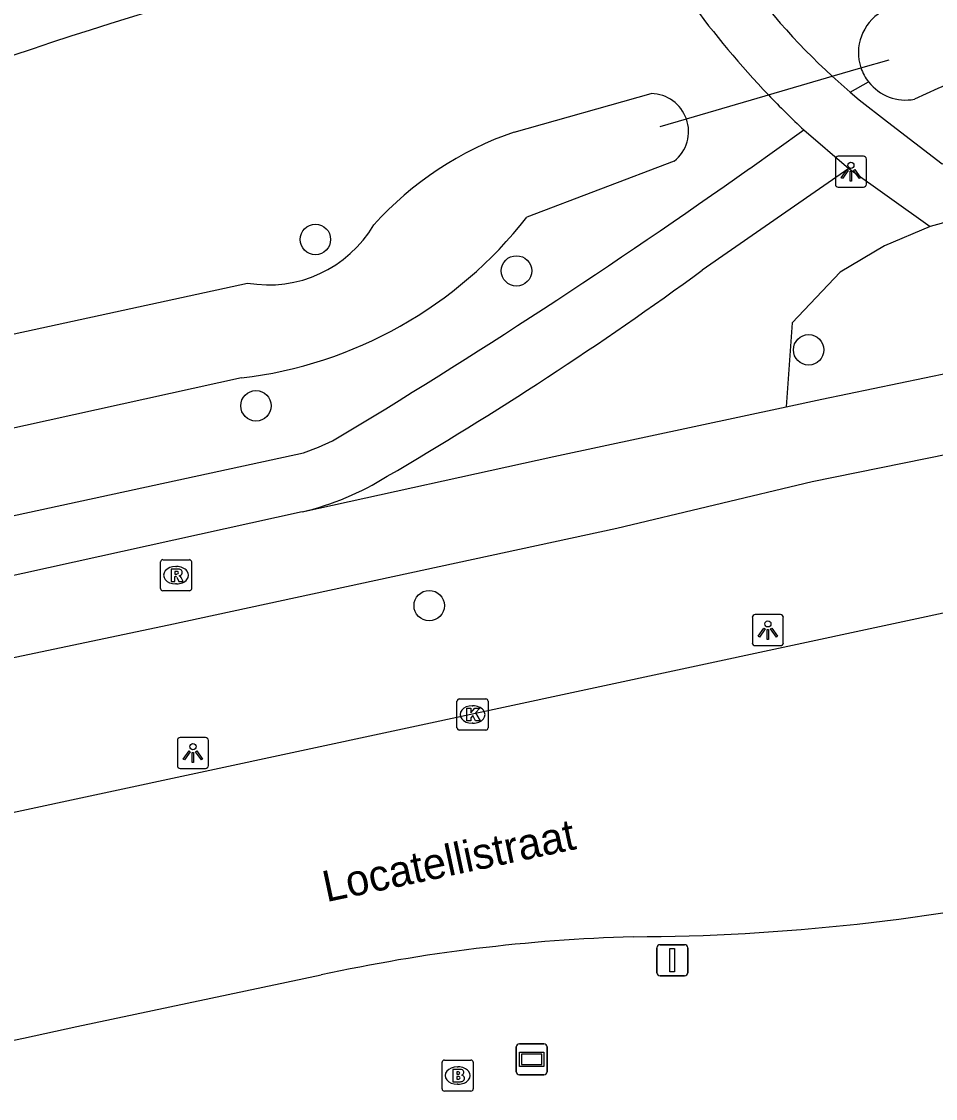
# Model space of a CAD drawing. Extents: x 159053 to 160041, y 380450 to 381422.
# Drawn here: x 159231.84 to 159261.22, y 380743.22 to 380777.85 of the extents above; entities that cross this region are included whole.
import ezdxf

# ---------------------------------------------------------------- set-up
doc = ezdxf.new("R2010")
doc.units = 0
for name, color, linetype in [('IMGEO_Boom', 7, 'Continuous'), ('IMGEO_Brandkraan', 7, 'Continuous'), ('IMGEO_Duiker', 7, 'Continuous'), ('IMGEO_Fietspad_gesloten', 7, 'Continuous'), ('IMGEO_Groenvoorziening', 7, 'Continuous'), ('IMGEO_Kolk', 7, 'Continuous'), ('IMGEO_Lichtpunt', 7, 'Continuous'), ('IMGEO_Openbare_ruimte_label', 7, 'Continuous'), ('IMGEO_Rijbaan_lokaal_gesloten', 7, 'Continuous'), ('IMGEO_Rioolput', 7, 'Continuous'), ('IMGEO_Verkeersbordpaal', 7, 'Continuous'), ('IMGEO_Verklikker', 7, 'Continuous'), ('IMGEO_Voetpad_open', 7, 'Continuous'), ('IMGEO_Waterloop', 7, 'Continuous')]:
    doc.layers.add(name, color=color, linetype=linetype)

msp = doc.modelspace()

# ---------------------------------------------------------------- linework, layer by layer
at = {"layer": 'IMGEO_Boom'}
for centre in [(159241.291, 380770.84), (159247.754, 380769.829), (159257.145, 380767.29), (159239.38, 380765.491), (159244.949, 380759.065)]:
    msp.add_circle(centre, 0.489, dxfattribs=at)
at = {"layer": 'IMGEO_Brandkraan'}
for p, q in [((159245.438, 380744.453), (159246.29, 380744.453)), ((159245.363, 380743.527), (159245.363, 380744.379)), ((159245.851, 380744.233), (159245.876, 380744.233)), ((159246.364, 380744.379), (159246.364, 380743.527)), ((159246.29, 380743.453), (159245.438, 380743.453)), ((159245.874, 380743.673), (159245.849, 380743.673))]:
    msp.add_line(p, q, dxfattribs=at)
for points in [[(159245.438, 380744.453), (159246.29, 380744.453)], [(159245.363, 380743.527), (159245.363, 380744.379)], [(159245.711, 380744.153), (159245.711, 380743.753), (159245.924, 380743.753)], [(159245.942, 380744.153), (159245.711, 380744.153)], [(159246.364, 380744.379), (159246.364, 380743.527)], [(159245.89, 380744.072), (159245.836, 380744.072), (159245.836, 380743.996)], [(159245.836, 380743.996), (159245.889, 380743.996)], [(159245.898, 380743.92), (159245.836, 380743.92), (159245.836, 380743.839)], [(159245.836, 380743.839), (159245.898, 380743.839)], [(159246.29, 380743.453), (159245.438, 380743.453)]]:
    msp.add_lwpolyline(points, dxfattribs=at)
for centre, radius, start, end in [((159245.44, 380744.377), 0.0765, 91.552, 178.448), ((159245.44, 380744.377), 0.0765, 91.552, 178.448), ((159246.288, 380744.377), 0.0765, 1.552, 88.448), ((159246.288, 380744.377), 0.0765, 1.552, 88.448), ((159245.946, 380744.008), 0.145, 59.4692, 91.5367), ((159245.971, 380744.055), 0.0922, 285.5137, 58.1501), ((159245.891, 380744.034), 0.0379, 267.8285, 90.9355), ((159245.899, 380743.879), 0.0404, 269.8759, 90.5077), ((159245.93, 380744.004), 0.251, 268.6676, 293.5347), ((159245.976, 380743.863), 0.105, 301.3115, 78.989), ((159245.44, 380743.529), 0.0765, 181.552, 268.448), ((159245.44, 380743.529), 0.0765, 181.552, 268.448), ((159246.288, 380743.529), 0.0765, 271.552, 358.448), ((159246.288, 380743.529), 0.0765, 271.552, 358.448)]:
    msp.add_arc(centre, radius, start, end, dxfattribs=at)
for centre, major_axis, ratio, start_param, end_param in [((159245.85, 380743.953), (-0.387, 0.002), 0.722429, 4.712389, 7.853982), ((159245.875, 380743.953), (-0.39, 0.002), 0.717154, 1.570796, 4.712389)]:
    msp.add_ellipse(centre, major_axis=major_axis, ratio=ratio, start_param=start_param, end_param=end_param, dxfattribs=at)
at = {"layer": 'IMGEO_Duiker'}
msp.add_lwpolyline([(159252.374, 380774.473), (159253.216, 380774.719), (159255.747, 380775.458), (159255.854, 380775.489), (159257.719, 380776.033), (159257.904, 380776.087), (159258.828, 380776.357), (159259.732, 380776.621)], dxfattribs=at)
at = {"layer": 'IMGEO_Fietspad_gesloten'}
for points in [[(159256.423, 380765.457), (159257.575, 380765.703), (159263.34, 380766.906)], [(159240.86, 380762.077), (159248.952, 380763.865), (159256.423, 380765.457)], [(159215.224, 380754.658), (159220.197, 380755.183), (159224.095, 380755.817), (159236.577, 380758.45), (159250.976, 380761.561), (159257.264, 380763.056), (159263.863, 380764.398)], [(159240.86, 380762.077), (159228.577, 380759.365), (159223.632, 380758.213), (159221.177, 380757.811)]]:
    msp.add_lwpolyline(points, dxfattribs=at)
at = {"layer": 'IMGEO_Groenvoorziening'}
for points in [[(159258.48, 380775.578), (159259.075, 380775.904)], [(159261.051, 380771.257), (159259.589, 380770.637), (159258.163, 380769.793), (159256.621, 380768.163), (159256.423, 380765.457)]]:
    msp.add_lwpolyline(points, dxfattribs=at)
at = {"layer": 'IMGEO_Kolk'}
for p, q in [((159245.842, 380755.138), (159245.842, 380755.99)), ((159245.917, 380756.064), (159246.769, 380756.064)), ((159246.843, 380755.99), (159246.843, 380755.138)), ((159246.33, 380755.844), (159246.355, 380755.844)), ((159246.353, 380755.284), (159246.328, 380755.284)), ((159246.769, 380755.064), (159245.917, 380755.064))]:
    msp.add_line(p, q, dxfattribs=at)
for points in [[(159245.842, 380755.138), (159245.842, 380755.99)], [(159245.917, 380756.064), (159246.769, 380756.064)], [(159246.843, 380755.99), (159246.843, 380755.138)], [(159246.163, 380755.764), (159246.286, 380755.764), (159246.286, 380755.613), (159246.416, 380755.764), (159246.58, 380755.764), (159246.434, 380755.613), (159246.587, 380755.364), (159246.435, 380755.364), (159246.35, 380755.528), (159246.286, 380755.461), (159246.286, 380755.364), (159246.163, 380755.364), (159246.163, 380755.764)], [(159246.769, 380755.064), (159245.917, 380755.064)]]:
    msp.add_lwpolyline(points, dxfattribs=at)
for centre, start, end in [((159245.919, 380755.988), 91.552, 178.448), ((159245.919, 380755.988), 91.552, 178.448), ((159246.767, 380755.988), 1.552, 88.448), ((159246.767, 380755.988), 1.552, 88.448), ((159245.919, 380755.14), 181.552, 268.448), ((159245.919, 380755.14), 181.552, 268.448), ((159246.767, 380755.14), 271.552, 358.448), ((159246.767, 380755.14), 271.552, 358.448)]:
    msp.add_arc(centre, 0.0765, start, end, dxfattribs=at)
for centre, major_axis, ratio, start_param, end_param in [((159246.329, 380755.564), (-0.387, 0.002), 0.722429, 4.712389, 7.853982), ((159246.354, 380755.564), (-0.39, 0.002), 0.717154, 1.570796, 4.712389)]:
    msp.add_ellipse(centre, major_axis=major_axis, ratio=ratio, start_param=start_param, end_param=end_param, dxfattribs=at)
at = {"layer": 'IMGEO_Lichtpunt'}
for p, q in [((159258.005, 380773.424), (159258.005, 380772.617)), ((159258.005, 380773.424), (159258.005, 380772.617)), ((159258.907, 380773.519), (159258.099, 380773.519)), ((159258.907, 380773.519), (159258.099, 380773.519)), ((159259.001, 380772.617), (159259.001, 380773.424)), ((159259.001, 380772.617), (159259.001, 380773.424)), ((159258.099, 380772.523), (159258.907, 380772.523)), ((159258.099, 380772.523), (159258.907, 380772.523)), ((159255.336, 380758.681), (159255.336, 380757.874)), ((159255.336, 380758.681), (159255.336, 380757.874)), ((159256.238, 380758.776), (159255.43, 380758.776)), ((159256.238, 380758.776), (159255.43, 380758.776)), ((159256.332, 380757.874), (159256.332, 380758.681)), ((159256.332, 380757.874), (159256.332, 380758.681)), ((159255.43, 380757.78), (159256.238, 380757.78)), ((159255.43, 380757.78), (159256.238, 380757.78)), ((159236.854, 380754.729), (159236.854, 380753.922)), ((159236.854, 380754.729), (159236.854, 380753.922)), ((159237.756, 380754.824), (159236.948, 380754.824)), ((159237.756, 380754.824), (159236.948, 380754.824)), ((159237.85, 380753.922), (159237.85, 380754.729)), ((159237.85, 380753.922), (159237.85, 380754.729)), ((159236.948, 380753.828), (159237.756, 380753.828)), ((159236.948, 380753.828), (159237.756, 380753.828))]:
    msp.add_line(p, q, dxfattribs=at)
for points in [[(159258.379, 380773.088), (159258.418, 380773.06), (159258.23, 380772.798), (159258.192, 380772.825), (159258.379, 380773.088)], [(159258.481, 380773.04), (159258.528, 380773.04), (159258.528, 380772.718), (159258.481, 380772.718), (159258.481, 380773.04)], [(159258.591, 380773.06), (159258.629, 380773.087), (159258.816, 380772.825), (159258.777, 380772.797), (159258.591, 380773.06)], [(159255.71, 380758.345), (159255.749, 380758.317), (159255.561, 380758.055), (159255.523, 380758.082), (159255.71, 380758.345)], [(159255.812, 380758.297), (159255.859, 380758.297), (159255.859, 380757.975), (159255.812, 380757.975), (159255.812, 380758.297)], [(159255.922, 380758.317), (159255.96, 380758.344), (159256.147, 380758.082), (159256.108, 380758.054), (159255.922, 380758.317)], [(159237.228, 380754.393), (159237.267, 380754.365), (159237.079, 380754.103), (159237.041, 380754.13), (159237.228, 380754.393)], [(159237.33, 380754.345), (159237.377, 380754.345), (159237.377, 380754.023), (159237.33, 380754.023), (159237.33, 380754.345)], [(159237.44, 380754.365), (159237.478, 380754.392), (159237.665, 380754.13), (159237.626, 380754.102), (159237.44, 380754.365)]]:
    msp.add_lwpolyline(points, dxfattribs=at)
for centre in [(159258.504, 380773.222), (159255.835, 380758.479), (159237.353, 380754.527)]:
    msp.add_circle(centre, 0.0994, dxfattribs=at)
for centre, start, end in [((159258.099, 380773.424), 90, 180), ((159258.099, 380773.424), 90, 180), ((159258.907, 380773.424), 0, 90), ((159258.907, 380773.424), 0, 90), ((159258.099, 380772.617), 180, 270), ((159258.099, 380772.617), 180, 270), ((159258.907, 380772.617), 270, 0), ((159258.907, 380772.617), 270, 360), ((159255.43, 380758.681), 90, 180), ((159255.43, 380758.681), 90, 180), ((159256.238, 380758.681), 0, 90), ((159256.238, 380758.681), 0, 90), ((159255.43, 380757.874), 180, 270), ((159255.43, 380757.874), 180, 270), ((159256.238, 380757.874), 270, 0), ((159256.238, 380757.874), 270, 360), ((159236.948, 380754.729), 90, 180), ((159236.948, 380754.729), 90, 180), ((159237.756, 380754.729), 0, 90), ((159237.756, 380754.729), 0, 90), ((159236.948, 380753.922), 180, 270), ((159236.948, 380753.922), 180, 270), ((159237.756, 380753.922), 270, 0), ((159237.756, 380753.922), 270, 360)]:
    msp.add_arc(centre, 0.0946, start, end, dxfattribs=at)
at = {"layer": 'IMGEO_Rijbaan_lokaal_gesloten'}
for points in [[(159265.764, 380759.746), (159225.045, 380751.009), (159219.931, 380750)], [(159223.158, 380743.217), (159226.529, 380744.028), (159231.908, 380745.154), (159233.625, 380745.533), (159241.475, 380747.19)]]:
    msp.add_lwpolyline(points, dxfattribs=at)
for centre, radius, start, end in [((159251.289, 380815.931), 67.514, 270.1809, 282.4292), ((159253.137, 380693.52), 54.922, 91.7055, 102.2589)]:
    msp.add_arc(centre, radius, start, end, dxfattribs=at)
at = {"layer": 'IMGEO_Rioolput'}
for p, q in [((159236.312, 380759.617), (159236.312, 380760.469)), ((159236.387, 380760.543), (159237.239, 380760.543)), ((159237.313, 380760.469), (159237.313, 380759.617)), ((159236.8, 380760.323), (159236.825, 380760.323)), ((159236.823, 380759.763), (159236.798, 380759.763)), ((159237.239, 380759.543), (159236.387, 380759.543))]:
    msp.add_line(p, q, dxfattribs=at)
for points in [[(159236.312, 380759.617), (159236.312, 380760.469)], [(159236.387, 380760.543), (159237.239, 380760.543)], [(159237.313, 380760.469), (159237.313, 380759.617)], [(159236.901, 380760.241), (159236.649, 380760.243), (159236.649, 380759.843)], [(159236.827, 380760.162), (159236.773, 380760.162), (159236.773, 380760.081)], [(159236.773, 380760.081), (159236.825, 380760.081)], [(159236.649, 380759.843), (159236.773, 380759.843), (159236.773, 380760.005), (159236.784, 380760.005)], [(159236.831, 380759.976), (159236.902, 380759.843), (159237.042, 380759.843), (159236.977, 380759.969)], [(159237.239, 380759.543), (159236.387, 380759.543)]]:
    msp.add_lwpolyline(points, dxfattribs=at)
for centre, radius, start, end in [((159236.389, 380760.467), 0.0765, 91.552, 178.448), ((159236.389, 380760.467), 0.0765, 91.552, 178.448), ((159237.237, 380760.467), 0.0765, 1.552, 88.448), ((159237.237, 380760.467), 0.0765, 1.552, 88.448), ((159236.809, 380760.27), 0.19, 274.7715, 282.9687), ((159236.833, 380760.066), 0.0964, 77.0061, 93.1865), ((159236.847, 380760.123), 0.0378, 276.6634, 79.6772), ((159236.9, 380760.131), 0.109, 350.3612, 89.416), ((159236.898, 380760.131), 0.112, 277.5842, 350.9817), ((159236.783, 380759.952), 0.0533, 26.0293, 88.6989), ((159236.882, 380759.916), 0.108, 29.5134, 73.7905), ((159236.389, 380759.619), 0.0765, 181.552, 268.448), ((159236.389, 380759.619), 0.0765, 181.552, 268.448), ((159237.237, 380759.619), 0.0765, 271.552, 358.448), ((159237.237, 380759.619), 0.0765, 271.552, 358.448)]:
    msp.add_arc(centre, radius, start, end, dxfattribs=at)
for centre, major_axis, ratio, start_param, end_param in [((159236.799, 380760.043), (-0.387, 0.002), 0.722429, 4.712389, 7.853982), ((159236.824, 380760.043), (-0.39, 0.002), 0.717154, 1.570796, 4.712389)]:
    msp.add_ellipse(centre, major_axis=major_axis, ratio=ratio, start_param=start_param, end_param=end_param, dxfattribs=at)
at = {"layer": 'IMGEO_Verkeersbordpaal'}
for p, q in [((159252.269, 380747.262), (159252.269, 380748.062)), ((159252.269, 380748.062), (159252.269, 380747.262)), ((159252.369, 380748.162), (159253.159, 380748.162)), ((159253.159, 380748.162), (159252.369, 380748.162)), ((159253.259, 380748.062), (159253.259, 380747.262)), ((159253.259, 380747.262), (159253.259, 380748.062)), ((159253.159, 380747.162), (159252.369, 380747.162)), ((159252.369, 380747.162), (159253.159, 380747.162))]:
    msp.add_line(p, q, dxfattribs=at)
msp.add_lwpolyline([(159252.689, 380748.037), (159252.839, 380748.037), (159252.839, 380747.287), (159252.689, 380747.287), (159252.689, 380748.037)], dxfattribs=at)
for centre, start, end in [((159252.369, 380748.062), 90, 180), ((159252.369, 380748.062), 90, 180), ((159253.159, 380748.062), 0, 90), ((159253.159, 380748.062), 360, 90), ((159252.369, 380747.262), 180, 270), ((159252.369, 380747.262), 180, 270), ((159253.159, 380747.262), 270, 0), ((159253.159, 380747.262), 270, 0)]:
    msp.add_arc(centre, 0.1, start, end, dxfattribs=at)
at = {"layer": 'IMGEO_Verklikker'}
for p, q in [((159247.746, 380744.075), (159247.746, 380744.875)), ((159247.746, 380744.875), (159247.746, 380744.075)), ((159247.846, 380744.975), (159248.636, 380744.975)), ((159248.636, 380744.975), (159247.846, 380744.975)), ((159248.736, 380744.875), (159248.736, 380744.075)), ((159248.736, 380744.075), (159248.736, 380744.875)), ((159248.636, 380743.975), (159247.846, 380743.975)), ((159247.846, 380743.975), (159248.636, 380743.975))]:
    msp.add_line(p, q, dxfattribs=at)
for points in [[(159247.847, 380744.707), (159248.635, 380744.707), (159248.635, 380744.243), (159247.847, 380744.243), (159247.847, 380744.707)], [(159247.912, 380744.642), (159247.912, 380744.308), (159248.57, 380744.308), (159248.57, 380744.642), (159247.912, 380744.642)]]:
    msp.add_lwpolyline(points, dxfattribs=at)
for centre, start, end in [((159247.846, 380744.875), 90, 180), ((159247.846, 380744.875), 90, 180), ((159248.636, 380744.875), 0, 90), ((159248.636, 380744.875), 360, 90), ((159247.846, 380744.075), 180, 270), ((159247.846, 380744.075), 180, 270), ((159248.636, 380744.075), 270, 0), ((159248.636, 380744.075), 270, 0)]:
    msp.add_arc(centre, 0.1, start, end, dxfattribs=at)
at = {"layer": 'IMGEO_Voetpad_open'}
for points in [[(159257.904, 380776.087), (159258.19, 380775.83), (159258.48, 380775.578)], [(159258.48, 380775.578), (159258.774, 380775.331), (159259.684, 380774.622), (159261.439, 380773.27), (159264.545, 380774.097), (159266.37, 380767.539)], [(159255.25, 380773.126), (159256.991, 380774.362)], [(159256.991, 380774.362), (159258.439, 380773.12)], [(159258.439, 380773.12), (159253.727, 380769.849)], [(159258.439, 380773.12), (159261.051, 380771.257)], [(159264.623, 380767.174), (159263.285, 380771.872), (159261.051, 380771.257)], [(159221.451, 380759.762), (159240.908, 380763.979), (159241.388, 380764.162), (159241.839, 380764.36)]]:
    msp.add_lwpolyline(points, dxfattribs=at)
for centre, radius, start, end in [((159274.059, 380652.272), 131.534, 99.98701, 109.13594), ((159277.175, 380795.857), 29.486, 208.4435, 223.6909), ((159272.449, 380791.967), 21.534, 214.758, 227.5125), ((159277.682, 380796.374), 30.21, 223.7348, 226.7714), ((159133.712, 380944.423), 210.034, 300.98449, 305.35619), ((159183.118, 380866.714), 119.868, 300.30279, 306.0899), ((159238.657, 380771.194), 9.379, 283.5869, 301.8072)]:
    msp.add_arc(centre, radius, start, end, dxfattribs=at)
at = {"layer": 'IMGEO_Waterloop'}
for points in [[(159247.677, 380774.295), (159252.087, 380775.529)], [(159252.824, 380773.357), (159248.084, 380771.553)], [(159203.563, 380762.47), (159206.134, 380762.274), (159239.111, 380769.439)], [(159238.914, 380766.387), (159225.746, 380763.484)]]:
    msp.add_lwpolyline(points, dxfattribs=at)
for centre, radius, start, end in [((159260.27, 380776.85), 1.524, 120.7092, 198.8558), ((159268.109, 380760.022), 17.09, 72.3043, 116.2512), ((159260.261, 380776.845), 1.514, 198.7883, 218.4149), ((159260.271, 380776.847), 1.523, 218.2576, 280.5707), ((159252.068, 380774.311), 1.218, 19.5674, 89.1176), ((159252.066, 380774.313), 1.22, 308.4316, 19.4555), ((159251.249, 380763.999), 10.898, 109.1336, 137.8466), ((159237.307, 380779.962), 13.67, 276.7529, 322.0373), ((159239.79, 380773.301), 3.921, 260.0277, 329.5369)]:
    msp.add_arc(centre, radius, start, end, dxfattribs=at)

# ---------------------------------------------------------------- texts
at = {"layer": 'IMGEO_Openbare_ruimte_label'}
msp.add_text('Locatellistraat', height=1, rotation=12.0067, dxfattribs=at).set_placement((159241.643, 380749.527))

doc.saveas('drawing.dxf')
